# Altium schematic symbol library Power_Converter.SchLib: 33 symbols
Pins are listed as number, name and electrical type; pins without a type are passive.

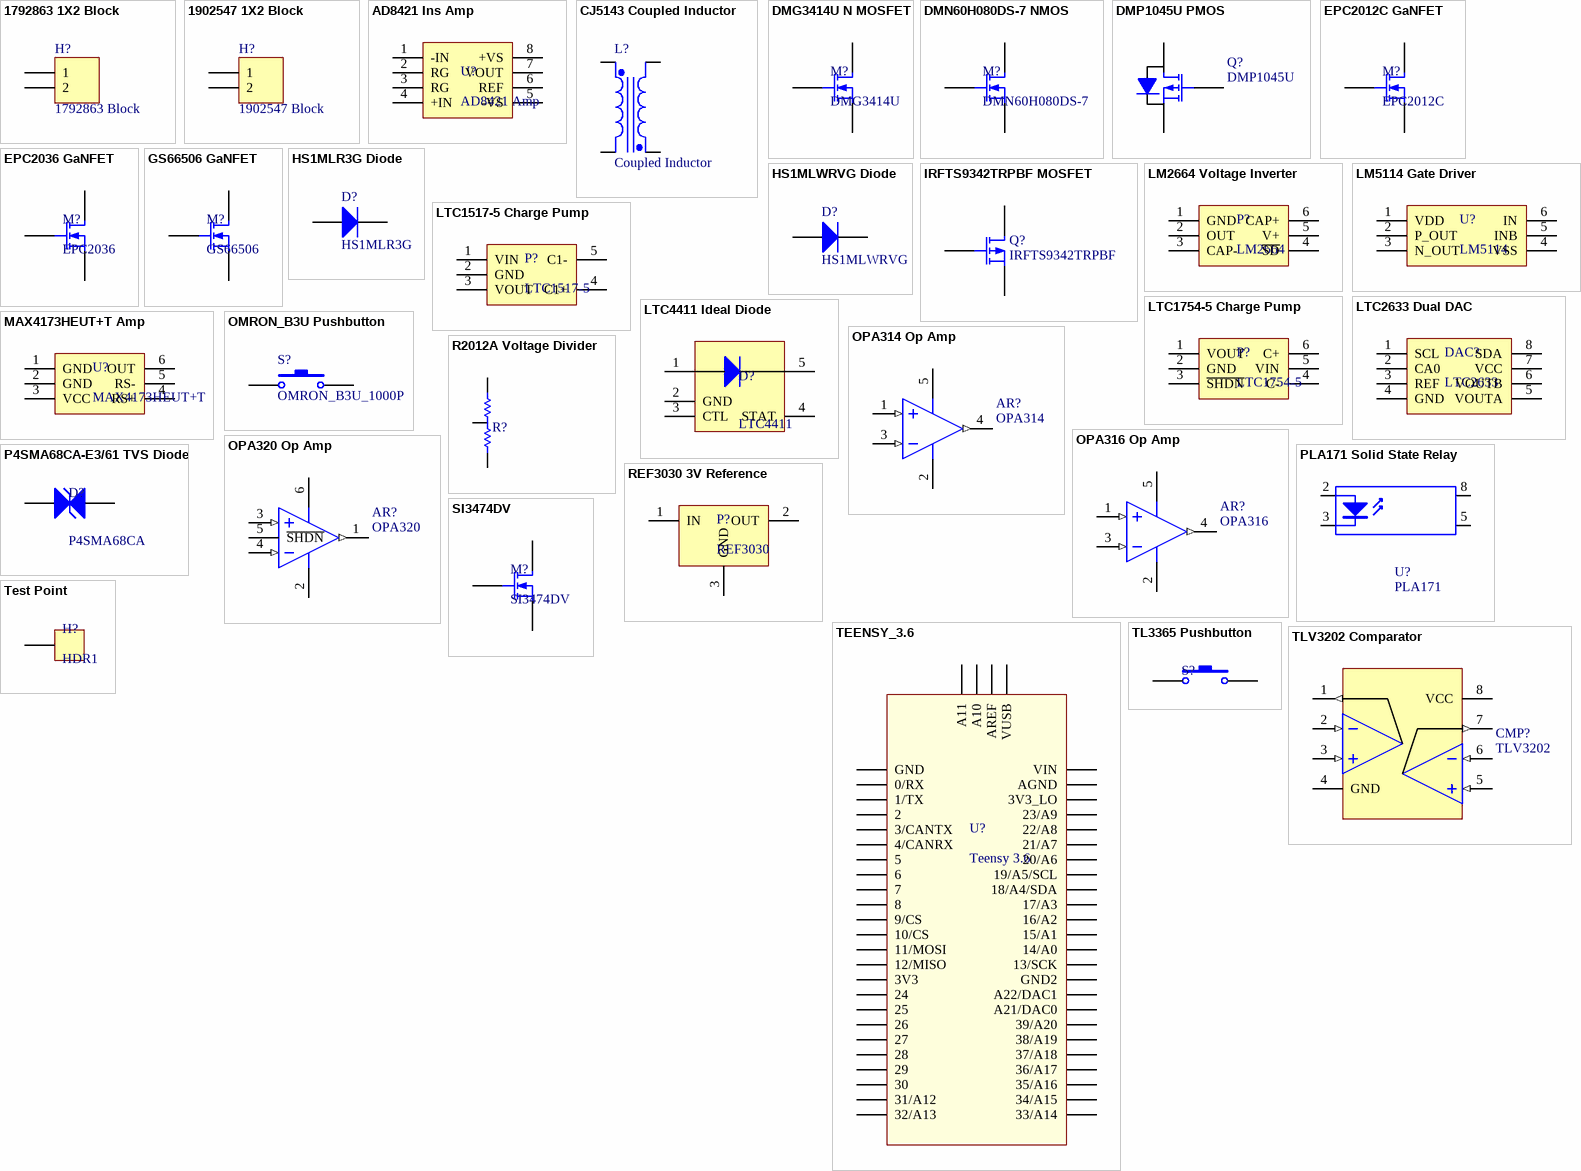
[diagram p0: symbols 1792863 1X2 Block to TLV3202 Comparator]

## 1792863 1X2 Block
designator H?, comment 1792863 Block
Terminal Block, 2-Pin, 1792863
signal-integrity model Connector
footprint PHX_BLOCK_SMALLER
pins: 1, 2

## 1902547 1X2 Block
designator H?, comment 1902547 Block
Terminal Block, 2-Pin, 1902547
signal-integrity model Connector
footprint PHX_BLOCK
pins: 1, 2

## AD8421 Ins Amp
designator U?, comment AD8421 Amp
Instrumentation Amplifier
footprint VSSOP8
pins: 1 -IN, 2 RG, 3 RG, 4 +IN, 5 -VS, 6 REF, 7 VOUT, 8 +VS

## CJ5143 Coupled Inductor
designator L?, comment Coupled Inductor
1:15 Coupled Inductor
simulation model TRANSFORMER (Transformer)
footprint CJ5143 Inductor
pins: 1 Pri+, 4 Pri-, 5 Sec-, 6 Sec+

## DMG3414U N MOSFET
designator M?, comment DMG3414U
20V, 0.5Vgs N-channel MOSFET
footprint SOT23_N (SOT23, 3-Leads, Body 2.9x1.3mm, Pitch 0.95mm, Lead Span 2.3mm - Reverse Pinning, IPC Medium Density)
pins: 1 D, 2 S, 3 G

## DMN60H080DS-7 NMOS
designator M?, comment DMN60H080DS-7
600V N-channel MOSFET
footprint SOT23_N (SOT23, 3-Leads, Body 2.9x1.3mm, Pitch 0.95mm, Lead Span 2.3mm - Reverse Pinning, IPC Medium Density)
pins: 1 D, 2 S, 3 G

## DMP1045U PMOS
designator Q?, comment DMP1045U
P-Channel MOSFET
simulation model PMOS (MOSFET-P)
footprint SOT23_N (SOT23, 3-Leads, Body 2.9x1.3mm, Pitch 0.95mm, Lead Span 2.3mm - Reverse Pinning, IPC Medium Density)
pins: 1 D, 2 S, 3 G

## EPC2012C GaNFET
designator M?, comment EPC2012C
200V GaNFET Die
footprint EPC2012C
pins: 1 G, 2 S, 3 D, 4 S

## EPC2036 GaNFET
designator M?, comment EPC2036
100V GaNFET Die
footprint BGA4x2
pins: 1 G, 2 S, 3 D, 4 S hidden to 2

## GS66506 GaNFET
designator M?, comment GS66506
650V GaNFET
footprint GS66506T
pins: 1 D, 2 G, 3 S, 4 G

## HS1MLR3G Diode
designator D?, comment HS1MLR3G
1kV fast diode
simulation model DIODE (Diode)
signal-integrity model Diode
footprint sub-SMA; pin to pad 1>A 2>K
pins: 1 A, 2 K

## HS1MLWRVG Diode
designator D?, comment HS1MLWRVG
1kV fast diode
simulation model DIODE (Diode)
signal-integrity model Diode
footprint sub-SMA
pins: A, K

## IRFTS9342TRPBF MOSFET
designator Q?, comment IRFTS9342TRPBF
30V, 5.8A, P-Channel MOSFET
simulation model PMOS (MOSFET-P)
footprint SOT23-6_N (SOT23, 6-Leads, Body 2.9x1.6mm, Pitch 0.95mm, Lead Span 2.7mm, IPC Medium Density)
pins: 1 D, 2 D, 3 G, 4 S, 5 D, 6 D

## LM2664 Voltage Inverter
designator P?, comment LM2664
Voltage Inverter
footprint SOT23-6_N (SOT23, 6-Leads, Body 2.9x1.6mm, Pitch 0.95mm, Lead Span 2.7mm, IPC Medium Density)
pins: 1 GND, 2 OUT, 3 CAP-, 4 ~{SD}, 5 V+, 6 CAP+

## LM5114 Gate Driver
designator U?, comment LM5114
Gate Driver
footprint SOT23-6_N (SOT23, 6-Leads, Body 2.9x1.6mm, Pitch 0.95mm, Lead Span 2.7mm, IPC Medium Density)
pins: 1 VDD, 2 P_OUT, 3 N_OUT, 4 VSS, 5 INB, 6 IN

## LTC1517-5 Charge Pump
designator P?, comment LTC1517-5
5V Charge Pump
footprint SOT23-5
pins: 1 VIN, 2 GND, 3 VOUT, 4 C1+, 5 C1-

## LTC1754-5 Charge Pump
designator P?, comment LTC1754-5
5V Charge Pump
footprint SOT23-6_M (SOT23, 6-Leads, Body 2.9x1.6mm, Pitch 0.95mm, Lead Span 2.7mm, IPC Low Density)
pins: 1 VOUT, 2 GND, 3 ~{SHDN}, 4 C-, 5 VIN, 6 C+

## LTC2633 Dual DAC
designator DAC?, comment LTC2633
Dual DAC
footprint SOT23-8
pins: 1 SCL, 2 CA0, 3 REF, 4 GND, 5 VOUTA, 6 VOUTB, 7 VCC, 8 SDA

## LTC4411 Ideal Diode
designator D?, comment LTC4411
LTC4411 Ideal Diode
simulation model DIODE (Diode)
signal-integrity model Diode
footprint SOT23-5
pins: 1 IN, 2 GND, 3 CTL, 4 STAT, 5 OUT

## MAX4173HEUT+T Amp
designator U?, comment MAX4173HEUT+T
100V/V Current Sense Amplifier
footprint SOT23-6_N (SOT23, 6-Leads, Body 2.9x1.6mm, Pitch 0.95mm, Lead Span 2.7mm, IPC Medium Density)
pins: 1 GND, 2 GND, 3 VCC, 4 RS+, 5 RS-, 6 OUT

## OMRON_B3U Pushbutton
designator S?, comment OMRON_B3U_1000P
Pushbutton
footprint OMRON_PUSHBUTTON
pins: 1, 2

## OPA314 Op Amp
designator AR?, comment OPA314
FET Operational Amplifier
simulation model AD645A (Spice Subcircuit)
footprint SC70-5
pins: 1 IN+ (in), 2 V- (power), 3 IN- (in), 4 OUT (out), 5 V+ (power)

## OPA316 Op Amp
designator AR?, comment OPA316
FET Operational Amplifier
simulation model AD645A (Spice Subcircuit)
footprint SC70-5
pins: 1 IN+ (in), 2 V- (power), 3 IN- (in), 4 OUT (out), 5 V+ (power)

## OPA320 Op Amp
designator AR?, comment OPA320
FET Operational Amplifier
simulation model AD645A (Spice Subcircuit)
footprint SOT23-6_M (SOT23, 6-Leads, Body 2.9x1.6mm, Pitch 0.95mm, Lead Span 2.7mm, IPC Low Density)
pins: 1 OUT (out), 2 V- (power), 3 IN+ (in), 4 IN- (in), 5 ~{SHDN}, 6 V+ (power)

## P4SMA68CA-E3/61 TVS Diode
designator D?, comment P4SMA68CA
TVS Diode
simulation model ZENER (Diode)
signal-integrity model D Zener
footprint DO-214AC; pin to pad 1>A 2>K
pins: 1 A, 2 K

## PLA171 Solid State Relay
designator U?, comment PLA171
800V Solid State Relay
simulation model OPTOISO (Spice Subcircuit)
footprint SOP8
pins: 2 A "Anode", 3 K "Cathode", 5 E "Emitter", 8 C "Collector"

## R2012A Voltage Divider
designator R?, comment R2012A  (value not drawn)
Voltage Divider
simulation model RESISTOR (Resistor)
signal-integrity model Res
footprint R2012A (Voltage Divider 0805 Footprint)
pins: 1, 2, 3

## REF3030 3V Reference
designator P?, comment REF3030
3V Reference
footprint SOT23_N (SOT23, 3-Leads, Body 2.9x1.3mm, Pitch 0.95mm, Lead Span 2.3mm - Reverse Pinning, IPC Medium Density); pin to pad 1>3 3>1
pins: 1 IN, 2 OUT, 3 GND

## SI3474DV
designator M?
100V N MOSFET
footprint SOT23-6_N (SOT23, 6-Leads, Body 2.9x1.6mm, Pitch 0.95mm, Lead Span 2.7mm, IPC Medium Density)
pins: 1 D, 2 D, 3 G, 4 S, 5 D, 6 D

## TEENSY_3.6
designator U?, comment Teensy 3.6
Teensy 3.6 Microcontroller
footprint Teensy 3.6
pins: 0/RX, 1/TX, 2, 3/CANTX, 3V3, 3V3_LO, 4/CANRX, 5, 6, 7, 8, 9/CS, 10/CS, 11/MOSI, 12/MISO, 13/SCK, 14/A0, 15/A1, 16/A2, 17/A3, 18/A4/SDA, 19/A5/SCL, 20/A6, 21/A7, 21/DAC0 A21/DAC0, 22/A8, 23/A9, 24, 25, 26, 27, 28, 29, 30, 31/A12, 32/A13, 33/A14, 34/A15, 35/A16, 36/A17, 37/A18, 38/A19, 39/A20, A10, A11, A22/DAC1, AGND, AREF, GND, GND2, VIN, VUSB

## Test Point
designator H?, comment HDR1
0.1" Header 1x1
footprint Single Header
pins: 1

## TL3365 Pushbutton
designator S?, comment TL3365  (value not drawn)
Pushbutton
footprint TL3365 (Pushbutton)
pins: 1, 2, 3, 4

## TLV3202 Comparator
designator CMP?, comment TLV3202
Dual Comparator
simulation model AD645A (Spice Subcircuit)
footprint VSSOP8
pins: 1 OUT1 (out), 2 IN1- (in), 3 IN1+ (in), 4 GND, 5 IN2+ (in), 6 IN2- (in), 7 OUT2 (out), 8 VCC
